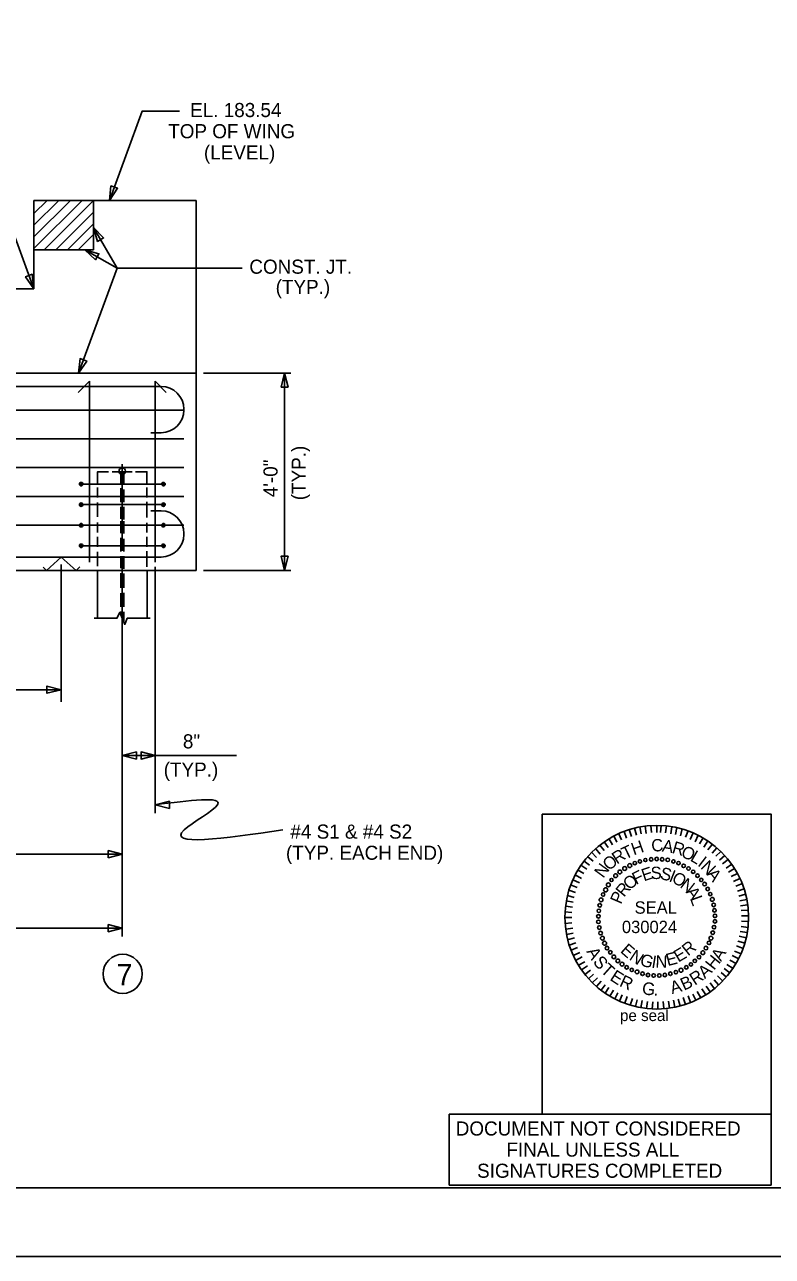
# Model space of a CAD drawing. Extents: x -41 to 251, y -169 to 237.
# Drawn here: x 134.78 to 149.93, y -50.55 to -25.59 of the extents above; entities that cross this region are included whole.
import ezdxf

# ---------------------------------------------------------------- set-up
doc = ezdxf.new("R2010")
doc.units = 0
for name, color, linetype in [('Arrowhead Terminators', 7, 'Continuous'), ('Arrowhead Terminators CELL', 7, 'Continuous'), ('Beam Bolsters CELL', 7, 'Continuous'), ('Dimension Lines', 7, 'Continuous'), ('Mis Object Lines', 7, 'Continuous'), ('Peseal', 7, 'Continuous'), ('Plan Sheet CELL', 7, 'Continuous'), ('Plot Shape CELL', 7, 'Continuous'), ('Rebar Lines', 7, 'Continuous'), ('Rebar Lines CELL', 7, 'Continuous'), ('Sheet Sticker Exception Certification CELL', 7, 'Continuous'), ('Text', 7, 'Continuous'), ('Title Text', 7, 'Continuous'), ('User Information Notes', 7, 'Continuous'), ('User Information Notes CELL', 7, 'Continuous')]:
    doc.layers.add(name, color=color, linetype=linetype)

msp = doc.modelspace()

# ---------------------------------------------------------------- linework, layer by layer
at = {"layer": 'Arrowhead Terminators'}
for points in [[(139.98, -32.938), (140.052, -32.652), (140.123, -32.938)], [(140.123, -36.366), (140.052, -36.652), (139.98, -36.366)], [(136.477, -42.474), (136.763, -42.402), (136.477, -42.331)]]:
    msp.add_lwpolyline(points, close=True, dxfattribs=at)
at = {"layer": 'Arrowhead Terminators CELL'}
for points in [[(136.501, -29.152), (136.667, -28.908), (136.532, -28.859)], [(136.18, -29.701), (136.261, -29.985), (136.385, -29.914)], [(136.006, -30.152), (136.218, -30.357), (136.29, -30.233)], [(134.971, -30.944), (134.94, -30.65), (134.805, -30.7)], [(135.876, -32.652), (136.042, -32.408), (135.908, -32.359)], [(135.522, -39.069), (135.236, -39.141), (135.236, -38.997)], [(136.763, -40.402), (137.049, -40.331), (137.049, -40.474)], [(137.43, -40.402), (137.143, -40.474), (137.143, -40.331)], [(137.43, -41.402), (137.716, -41.474), (137.716, -41.331)], [(136.763, -43.902), (136.477, -43.831), (136.477, -43.974)]]:
    msp.add_lwpolyline(points, close=True, dxfattribs=at)
at = {"layer": 'Beam Bolsters CELL'}
for p, q in [((135.522, -36.381), (135.229, -36.654)), ((135.83, -36.653), (135.522, -36.381)), ((135.229, -36.654), (135.158, -36.583)), ((135.901, -36.582), (135.83, -36.653))]:
    msp.add_line(p, q, dxfattribs=at)
at = {"layer": 'Dimension Lines'}
for p, q in [((136.18, -29.701), (136.657, -30.528)), ((136.006, -30.152), (136.657, -30.528)), ((136.657, -30.528), (139.191, -30.528)), ((140.177, -32.652), (138.406, -32.652)), ((140.052, -32.652), (140.052, -36.652)), ((135.522, -36.533), (135.522, -39.313)), ((136.763, -36.652), (136.763, -44.069)), ((137.43, -36.579), (137.43, -41.569)), ((138.406, -36.652), (140.177, -36.652)), ((135.522, -39.069), (129.716, -39.069)), ((137.43, -40.402), (136.763, -40.402)), ((139.075, -40.402), (137.43, -40.402)), ((136.763, -42.402), (130.763, -42.402)), ((124.763, -43.902), (136.763, -43.902))]:
    msp.add_line(p, q, dxfattribs=at)
for points in [[(136.501, -29.152), (137.166, -27.341), (137.923, -27.341)], [(134.971, -30.944), (134.091, -28.546), (133.591, -28.546)], [(135.876, -32.652), (136.657, -30.528)]]:
    msp.add_lwpolyline(points, dxfattribs=at)
msp.add_circle((136.77, -44.828), 0.397, dxfattribs=at)
msp.add_spline([(137.43, -41.402), (138.694, -41.402), (138.017, -41.91), (140.014, -41.91)], degree=3, dxfattribs=at)
at = {"layer": 'Mis Object Lines'}
for p, q in [((134.971, -30.128), (135.947, -29.152)), ((134.971, -29.657), (135.476, -29.152)), ((134.971, -29.421), (135.24, -29.152)), ((134.971, -29.152), (134.971, -30.944)), ((134.971, -29.893), (135.712, -29.152)), ((138.263, -29.152), (134.971, -29.152)), ((135.183, -30.152), (136.18, -29.156)), ((136.18, -29.152), (136.18, -30.152)), ((138.263, -29.152), (138.263, -32.652)), ((135.419, -30.152), (136.18, -29.391)), ((135.655, -30.152), (136.18, -29.627)), ((135.869, -30.152), (136.18, -29.842)), ((136.18, -30.152), (134.971, -30.152)), ((125.859, -30.944), (134.971, -30.944)), ((99.263, -32.652), (138.263, -32.652)), ((138.263, -36.652), (138.263, -32.652)), ((132.886, -36.652), (138.263, -36.652))]:
    msp.add_line(p, q, dxfattribs=at)
at = {"layer": 'Peseal'}
for p, q in [((147.081, -42.043), (147.036, -41.9)), ((147.179, -42.016), (147.143, -41.873)), ((147.277, -41.99), (147.251, -41.846)), ((147.376, -41.981), (147.358, -41.838)), ((147.483, -41.963), (147.474, -41.82)), ((147.591, -41.963), (147.591, -41.82)), ((147.671, -41.963), (147.68, -41.82)), ((147.769, -41.972), (147.787, -41.829)), ((147.877, -41.99), (147.895, -41.846)), ((147.975, -42.007), (148.002, -41.864)), ((148.074, -42.034), (148.109, -41.891)), ((148.172, -42.061), (148.226, -41.927)), ((146.607, -42.267), (146.526, -42.151)), ((146.696, -42.213), (146.624, -42.088)), ((146.785, -42.16), (146.723, -42.034)), ((146.875, -42.115), (146.821, -41.99)), ((146.982, -42.079), (146.929, -41.945)), ((148.27, -42.106), (148.333, -41.972)), ((148.369, -42.151), (148.431, -42.016)), ((148.458, -42.195), (148.53, -42.07)), ((148.548, -42.258), (148.628, -42.133)), ((146.374, -42.473), (146.267, -42.365)), ((146.446, -42.401), (146.356, -42.294)), ((146.526, -42.33), (146.437, -42.222)), ((148.628, -42.312), (148.718, -42.204)), ((148.718, -42.383), (148.807, -42.276)), ((148.789, -42.446), (148.888, -42.347)), ((148.861, -42.526), (148.968, -42.428)), ((146.177, -42.705), (146.052, -42.625)), ((146.231, -42.625), (146.124, -42.544)), ((146.302, -42.544), (146.195, -42.455)), ((148.923, -42.598), (149.04, -42.508)), ((148.995, -42.687), (149.111, -42.607)), ((146.025, -42.983), (145.891, -42.92)), ((146.07, -42.893), (145.936, -42.822)), ((146.115, -42.795), (145.989, -42.723)), ((149.049, -42.768), (149.165, -42.696)), ((149.102, -42.857), (149.228, -42.795)), ((149.147, -42.956), (149.272, -42.893)), ((145.945, -43.179), (145.81, -43.135)), ((145.98, -43.081), (145.846, -43.027)), ((149.192, -43.054), (149.326, -43)), ((149.228, -43.152), (149.362, -43.108)), ((145.9, -43.376), (145.757, -43.349)), ((145.918, -43.278), (145.784, -43.242)), ((149.254, -43.251), (149.389, -43.215)), ((149.272, -43.349), (149.415, -43.322)), ((149.29, -43.448), (149.433, -43.43)), ((145.873, -43.582), (145.73, -43.573)), ((145.882, -43.475), (145.748, -43.457)), ((149.299, -43.546), (149.442, -43.537)), ((149.308, -43.653), (149.451, -43.653)), ((145.873, -43.689), (145.73, -43.689)), ((145.873, -43.797), (145.73, -43.806)), ((145.891, -43.904), (145.748, -43.922)), ((149.299, -43.868), (149.442, -43.886)), ((149.308, -43.761), (149.451, -43.77)), ((145.9, -44.002), (145.766, -44.029)), ((145.927, -44.101), (145.784, -44.136)), ((149.236, -44.163), (149.38, -44.208)), ((149.263, -44.065), (149.406, -44.101)), ((149.281, -43.967), (149.424, -43.993)), ((145.954, -44.199), (145.819, -44.244)), ((145.989, -44.297), (145.855, -44.351)), ((146.034, -44.396), (145.9, -44.459)), ((149.165, -44.369), (149.299, -44.423)), ((149.21, -44.262), (149.344, -44.315)), ((146.079, -44.485), (145.945, -44.557)), ((146.132, -44.584), (146.007, -44.655)), ((146.186, -44.664), (146.07, -44.745)), ((149.013, -44.637), (149.138, -44.718)), ((149.075, -44.548), (149.201, -44.62)), ((149.12, -44.459), (149.254, -44.521)), ((146.249, -44.754), (146.132, -44.843)), ((146.311, -44.834), (146.213, -44.924)), ((146.392, -44.906), (146.285, -45.013)), ((148.825, -44.87), (148.932, -44.977)), ((148.897, -44.798), (149.004, -44.897)), ((148.959, -44.718), (149.075, -44.807)), ((146.463, -44.977), (146.374, -45.085)), ((146.544, -45.049), (146.463, -45.156)), ((146.624, -45.103), (146.544, -45.219)), ((146.714, -45.156), (146.642, -45.281)), ((148.414, -45.183), (148.485, -45.317)), ((148.503, -45.129), (148.583, -45.255)), ((148.592, -45.076), (148.673, -45.192)), ((148.673, -45.013), (148.762, -45.129)), ((148.753, -44.951), (148.843, -45.049)), ((146.803, -45.21), (146.741, -45.335)), ((146.893, -45.255), (146.839, -45.38)), ((146.991, -45.29), (146.946, -45.425)), ((147.099, -45.326), (147.054, -45.46)), ((147.197, -45.353), (147.161, -45.487)), ((147.295, -45.371), (147.269, -45.514)), ((147.403, -45.389), (147.385, -45.532)), ((147.51, -45.398), (147.501, -45.541)), ((147.617, -45.398), (147.617, -45.541)), ((147.725, -45.389), (147.734, -45.532)), ((147.832, -45.38), (147.85, -45.523)), ((147.93, -45.362), (147.957, -45.505)), ((148.029, -45.344), (148.065, -45.478)), ((148.127, -45.308), (148.172, -45.451)), ((148.226, -45.273), (148.279, -45.407)), ((148.324, -45.237), (148.387, -45.362))]:
    msp.add_line(p, q, dxfattribs=at)
for centre, radius in [((146.942, -42.692), 0.0385), ((147.045, -42.634), 0.04), ((147.148, -42.584), 0.0341), ((147.251, -42.549), 0.0326), ((147.362, -42.522), 0.0316), ((147.479, -42.508), 0.0361), ((147.591, -42.499), 0.0358), ((147.702, -42.508), 0.0361), ((147.814, -42.517), 0.0369), ((147.93, -42.549), 0.0326), ((148.033, -42.584), 0.0341), ((148.136, -42.638), 0.0361), ((148.235, -42.692), 0.0361), ((146.674, -42.924), 0.0316), ((146.759, -42.839), 0.038), ((146.844, -42.763), 0.0385), ((148.329, -42.759), 0.0349), ((148.418, -42.839), 0.0349), ((148.494, -42.924), 0.0349), ((146.504, -43.22), 0.0341), ((146.557, -43.126), 0.0412), ((146.611, -43.023), 0.0385), ((148.561, -43.009), 0.0361), ((148.624, -43.108), 0.0361), ((148.677, -43.211), 0.0341), ((146.437, -43.439), 0.0369), ((146.463, -43.327), 0.0382), ((148.718, -43.318), 0.0382), ((148.745, -43.43), 0.0369), ((146.41, -43.662), 0.0358), ((146.419, -43.551), 0.0361), ((148.762, -43.542), 0.0361), ((148.771, -43.653), 0.0358), ((146.41, -43.774), 0.0361), ((146.428, -43.89), 0.0361), ((148.753, -43.882), 0.0361), ((148.771, -43.765), 0.0361), ((146.454, -44.002), 0.0369), ((146.49, -44.105), 0.0382), ((146.535, -44.208), 0.04), ((148.651, -44.199), 0.0361), ((148.691, -44.105), 0.0382), ((148.727, -43.993), 0.0369), ((146.584, -44.306), 0.0361), ((146.651, -44.391), 0.0349), ((148.525, -44.4), 0.0385), ((148.588, -44.306), 0.0361), ((146.723, -44.485), 0.038), ((146.803, -44.566), 0.038), ((146.888, -44.633), 0.0385), ((146.982, -44.696), 0.0361), ((148.19, -44.696), 0.0361), ((148.284, -44.637), 0.0349), ((148.364, -44.566), 0.0349), ((148.449, -44.49), 0.0349), ((147.085, -44.749), 0.0341), ((147.192, -44.789), 0.0382), ((147.304, -44.825), 0.0369), ((147.416, -44.852), 0.0361), ((147.528, -44.861), 0.0358), ((147.644, -44.861), 0.0358), ((147.756, -44.852), 0.0361), ((147.868, -44.825), 0.0369), ((147.98, -44.794), 0.0341), ((148.083, -44.754), 0.04)]:
    msp.add_circle(centre, radius, dxfattribs=at)
at = {"layer": 'Plan Sheet CELL'}
msp.add_line((88.128, -49.166), (161.409, -49.166), dxfattribs=at)
at = {"layer": 'Plot Shape CELL'}
msp.add_lwpolyline([(85.715, -0.174), (161.429, -0.174), (161.429, -50.554), (85.715, -50.554)], close=True, dxfattribs=at)
at = {"layer": 'Rebar Lines'}
for p, q in [((99.97, -32.923), (137.551, -32.923)), ((136.096, -32.819), (135.872, -33.043)), ((136.096, -36.485), (136.096, -32.819)), ((137.43, -36.485), (137.43, -32.819)), ((137.43, -32.819), (137.654, -33.043)), ((117.55, -33.402), (138.009, -33.402)), ((117.55, -33.986), (138.009, -33.986)), ((117.55, -34.569), (138.009, -34.569)), ((136.732, -34.895), (136.732, -34.652)), ((136.763, -34.501), (136.763, -36.257)), ((136.795, -34.901), (136.795, -34.652)), ((117.55, -35.152), (138.009, -35.152)), ((136.732, -35.267), (136.732, -34.988)), ((136.795, -35.267), (136.795, -35.011)), ((136.732, -35.609), (136.732, -35.36)), ((136.795, -35.621), (136.795, -35.36)), ((136.732, -35.895), (136.732, -35.652)), ((136.795, -35.901), (136.795, -35.652)), ((117.55, -35.735), (138.009, -35.735)), ((136.732, -36.267), (136.732, -35.988)), ((136.795, -36.267), (136.795, -36.011)), ((99.97, -36.381), (137.551, -36.381)), ((136.732, -36.609), (136.732, -36.36)), ((136.763, -36.362), (136.763, -36.652)), ((136.795, -36.621), (136.795, -36.36)), ((136.262, -36.669), (136.262, -37.621)), ((137.264, -36.669), (137.264, -37.621)), ((136.732, -37.004), (136.732, -36.708)), ((136.763, -36.722), (136.763, -37.928)), ((136.795, -37.004), (136.795, -36.714)), ((136.732, -37.388), (136.732, -37.115)), ((136.795, -37.388), (136.795, -37.109)), ((136.732, -37.556), (136.732, -37.481)), ((136.795, -37.705), (136.795, -37.492))]:
    msp.add_line(p, q, dxfattribs=at)
for points in [[(136.262, -34.886), (136.262, -34.652), (136.485, -34.652)], [(136.561, -34.652), (136.96, -34.652)], [(137.03, -34.652), (137.262, -34.652), (137.262, -34.899)], [(136.262, -35.176), (136.262, -34.968)], [(137.262, -34.974), (137.262, -35.173)], [(136.262, -35.564), (136.262, -35.272)], [(137.262, -35.259), (137.262, -35.58)], [(136.262, -35.886), (136.262, -35.678)], [(137.262, -35.684), (137.262, -35.883)], [(136.262, -36.176), (136.262, -35.968)], [(137.262, -35.974), (137.262, -36.173)], [(136.262, -36.564), (136.262, -36.272)], [(137.262, -36.259), (137.262, -36.58)], [(136.193, -37.622), (136.655, -37.622), (136.71, -37.502), (136.812, -37.747), (136.863, -37.622), (137.33, -37.622)]]:
    msp.add_lwpolyline(points, dxfattribs=at)
msp.add_circle((136.763, -34.641), 0.066, dxfattribs=at)
at = {"layer": 'Rebar Lines CELL'}
for p, q in [((138.009, -33.402), (138.009, -33.381)), ((137.342, -33.86), (137.551, -33.86)), ((137.596, -34.902), (135.93, -34.902)), ((137.596, -35.319), (135.93, -35.319)), ((137.342, -35.444), (137.551, -35.444)), ((137.596, -35.735), (135.93, -35.735)), ((138.009, -35.902), (138.009, -35.923)), ((137.596, -36.152), (135.93, -36.152))]:
    msp.add_line(p, q, dxfattribs=at)
for points in [[(135.93, -34.867), (135.916, -34.87), (135.905, -34.877), (135.897, -34.889), (135.894, -34.902), (135.897, -34.916), (135.905, -34.927), (135.916, -34.935), (135.93, -34.937), (135.943, -34.935), (135.955, -34.927), (135.962, -34.916), (135.965, -34.902), (135.962, -34.889), (135.955, -34.877), (135.943, -34.87), (135.93, -34.867), (135.93, -34.902), (135.93, -34.937), (135.916, -34.935), (135.93, -34.902), (135.905, -34.927), (135.897, -34.916), (135.93, -34.902), (135.894, -34.902), (135.897, -34.889), (135.93, -34.902), (135.905, -34.877), (135.916, -34.87), (135.93, -34.902), (135.943, -34.87), (135.955, -34.877), (135.93, -34.902), (135.962, -34.889), (135.965, -34.902), (135.93, -34.902), (135.962, -34.916), (135.955, -34.927), (135.93, -34.902), (135.943, -34.935)], [(137.596, -34.867), (137.583, -34.87), (137.571, -34.877), (137.564, -34.889), (137.561, -34.902), (137.564, -34.916), (137.571, -34.927), (137.583, -34.935), (137.596, -34.937), (137.61, -34.935), (137.621, -34.927), (137.629, -34.916), (137.632, -34.902), (137.629, -34.889), (137.621, -34.877), (137.61, -34.87), (137.596, -34.867), (137.596, -34.902), (137.596, -34.937), (137.583, -34.935), (137.596, -34.902), (137.571, -34.927), (137.564, -34.916), (137.596, -34.902), (137.561, -34.902), (137.564, -34.889), (137.596, -34.902), (137.571, -34.877), (137.583, -34.87), (137.596, -34.902), (137.61, -34.87), (137.621, -34.877), (137.596, -34.902), (137.629, -34.889), (137.632, -34.902), (137.596, -34.902), (137.629, -34.916), (137.621, -34.927), (137.596, -34.902), (137.61, -34.935)], [(135.93, -35.284), (135.916, -35.286), (135.905, -35.294), (135.897, -35.305), (135.894, -35.319), (135.897, -35.332), (135.905, -35.344), (135.916, -35.351), (135.93, -35.354), (135.943, -35.351), (135.955, -35.344), (135.962, -35.332), (135.965, -35.319), (135.962, -35.305), (135.955, -35.294), (135.943, -35.286), (135.93, -35.284), (135.93, -35.319), (135.93, -35.354), (135.916, -35.351), (135.93, -35.319), (135.905, -35.344), (135.897, -35.332), (135.93, -35.319), (135.894, -35.319), (135.897, -35.305), (135.93, -35.319), (135.905, -35.294), (135.916, -35.286), (135.93, -35.319), (135.943, -35.286), (135.955, -35.294), (135.93, -35.319), (135.962, -35.305), (135.965, -35.319), (135.93, -35.319), (135.962, -35.332), (135.955, -35.344), (135.93, -35.319), (135.943, -35.351)], [(137.596, -35.284), (137.583, -35.286), (137.571, -35.294), (137.564, -35.305), (137.561, -35.319), (137.564, -35.332), (137.571, -35.344), (137.583, -35.351), (137.596, -35.354), (137.61, -35.351), (137.621, -35.344), (137.629, -35.332), (137.632, -35.319), (137.629, -35.305), (137.621, -35.294), (137.61, -35.286), (137.596, -35.284), (137.596, -35.319), (137.596, -35.354), (137.583, -35.351), (137.596, -35.319), (137.571, -35.344), (137.564, -35.332), (137.596, -35.319), (137.561, -35.319), (137.564, -35.305), (137.596, -35.319), (137.571, -35.294), (137.583, -35.286), (137.596, -35.319), (137.61, -35.286), (137.621, -35.294), (137.596, -35.319), (137.629, -35.305), (137.632, -35.319), (137.596, -35.319), (137.629, -35.332), (137.621, -35.344), (137.596, -35.319), (137.61, -35.351)], [(135.93, -35.7), (135.916, -35.703), (135.905, -35.711), (135.897, -35.722), (135.894, -35.735), (135.897, -35.749), (135.905, -35.76), (135.916, -35.768), (135.93, -35.771), (135.943, -35.768), (135.955, -35.76), (135.962, -35.749), (135.965, -35.735), (135.962, -35.722), (135.955, -35.711), (135.943, -35.703), (135.93, -35.7), (135.93, -35.735), (135.93, -35.771), (135.916, -35.768), (135.93, -35.735), (135.905, -35.76), (135.897, -35.749), (135.93, -35.735), (135.894, -35.735), (135.897, -35.722), (135.93, -35.735), (135.905, -35.711), (135.916, -35.703), (135.93, -35.735), (135.943, -35.703), (135.955, -35.711), (135.93, -35.735), (135.962, -35.722), (135.965, -35.735), (135.93, -35.735), (135.962, -35.749), (135.955, -35.76), (135.93, -35.735), (135.943, -35.768)], [(137.596, -35.7), (137.583, -35.703), (137.571, -35.711), (137.564, -35.722), (137.561, -35.735), (137.564, -35.749), (137.571, -35.76), (137.583, -35.768), (137.596, -35.771), (137.61, -35.768), (137.621, -35.76), (137.629, -35.749), (137.632, -35.735), (137.629, -35.722), (137.621, -35.711), (137.61, -35.703), (137.596, -35.7), (137.596, -35.735), (137.596, -35.771), (137.583, -35.768), (137.596, -35.735), (137.571, -35.76), (137.564, -35.749), (137.596, -35.735), (137.561, -35.735), (137.564, -35.722), (137.596, -35.735), (137.571, -35.711), (137.583, -35.703), (137.596, -35.735), (137.61, -35.703), (137.621, -35.711), (137.596, -35.735), (137.629, -35.722), (137.632, -35.735), (137.596, -35.735), (137.629, -35.749), (137.621, -35.76), (137.596, -35.735), (137.61, -35.768)], [(135.93, -36.117), (135.916, -36.12), (135.905, -36.127), (135.897, -36.139), (135.894, -36.152), (135.897, -36.166), (135.905, -36.177), (135.916, -36.185), (135.93, -36.187), (135.943, -36.185), (135.955, -36.177), (135.962, -36.166), (135.965, -36.152), (135.962, -36.139), (135.955, -36.127), (135.943, -36.12), (135.93, -36.117), (135.93, -36.152), (135.93, -36.187), (135.916, -36.185), (135.93, -36.152), (135.905, -36.177), (135.897, -36.166), (135.93, -36.152), (135.894, -36.152), (135.897, -36.139), (135.93, -36.152), (135.905, -36.127), (135.916, -36.12), (135.93, -36.152), (135.943, -36.12), (135.955, -36.127), (135.93, -36.152), (135.962, -36.139), (135.965, -36.152), (135.93, -36.152), (135.962, -36.166), (135.955, -36.177), (135.93, -36.152), (135.943, -36.185)], [(137.596, -36.117), (137.583, -36.12), (137.571, -36.127), (137.564, -36.139), (137.561, -36.152), (137.564, -36.166), (137.571, -36.177), (137.583, -36.185), (137.596, -36.187), (137.61, -36.185), (137.621, -36.177), (137.629, -36.166), (137.632, -36.152), (137.629, -36.139), (137.621, -36.127), (137.61, -36.12), (137.596, -36.117), (137.596, -36.152), (137.596, -36.187), (137.583, -36.185), (137.596, -36.152), (137.571, -36.177), (137.564, -36.166), (137.596, -36.152), (137.561, -36.152), (137.564, -36.139), (137.596, -36.152), (137.571, -36.127), (137.583, -36.12), (137.596, -36.152), (137.61, -36.12), (137.621, -36.127), (137.596, -36.152), (137.629, -36.139), (137.632, -36.152), (137.596, -36.152), (137.629, -36.166), (137.621, -36.177), (137.596, -36.152), (137.61, -36.185)]]:
    msp.add_lwpolyline(points, dxfattribs=at)
for centre, start, end in [((137.551, -33.381), 0, 90), ((137.551, -33.402), 270, 0), ((137.551, -35.902), 0, 90), ((137.551, -35.923), 270, 0)]:
    msp.add_arc(centre, 0.458, start, end, dxfattribs=at)
at = {"layer": 'Sheet Sticker Exception Certification CELL'}
msp.add_lwpolyline([(143.386, -47.673), (149.909, -47.673), (149.909, -49.108), (143.386, -49.108)], close=True, dxfattribs=at)
at = {"layer": 'Text'}
msp.add_line((138.263, -36.652), (138.263, -36.652), dxfattribs=at)
at = {"layer": 'User Information Notes'}
msp.add_line((147.591, -43.68), (147.591, -43.68), dxfattribs=at)
at = {"layer": 'User Information Notes CELL'}
msp.add_line((147.591, -43.68), (147.591, -43.68), dxfattribs=at)
msp.add_lwpolyline([(145.272, -41.591), (149.909, -41.591), (149.909, -47.673), (145.272, -47.673)], close=True, dxfattribs=at)
msp.add_circle((147.591, -43.68), 1.861, dxfattribs=at)

# ---------------------------------------------------------------- texts
at = {"layer": 'Peseal'}
for s, height, rotation, p in [('H', 0.25, 18.9162, (147.125, -42.428)), ('C', 0.25, 4.8625, (147.492, -42.356)), ('A', 0.25, 350.8088, (147.689, -42.347)), ('R', 0.25, 343.7819, (147.886, -42.374)), ('R', 0.25, 32.9699, (146.785, -42.616)), ('T', 0.25, 25.943, (146.955, -42.517)), ('O', 0.25, 336.7551, (148.065, -42.446)), ('L', 0.25, 329.7282, (148.253, -42.526)), ('N', 0.25, 54.0504, (146.508, -42.902)), ('O', 0.25, 39.9967, (146.624, -42.75)), ('E', 0.25, 18.4448, (147.331, -42.956)), ('S', 0.25, 2.3789, (147.474, -42.911)), ('S', 0.25, 346.313, (147.644, -42.902)), ('I', 0.25, 322.7014, (148.405, -42.625)), ('N', 0.25, 315.6745, (148.467, -42.678)), ('O', 0.25, 42.5436, (147.045, -43.144)), ('F', 0.25, 26.4777, (147.17, -43.027)), ('I', 0.25, 338.28, (147.823, -42.947)), ('O', 0.25, 330.2471, (147.877, -42.956)), ('N', 0.25, 322.2141, (148.047, -43.063)), ('A', 0.25, 308.6477, (148.592, -42.813)), ('P', 0.25, 66.6424, (146.866, -43.43)), ('R', 0.25, 50.5765, (146.929, -43.287)), ('A', 0.25, 306.1483, (148.172, -43.17)), ('L', 0.25, 290.0824, (148.261, -43.296)), ('R', 0.25, 38.6997, (148.226, -44.476)), ('A', 0.254, 300.3993, (146.16, -44.375)), ('E', 0.25, 318.5179, (146.839, -44.378)), ('N', 0.25, 326.5361, (147.018, -44.53)), ('G', 0.25, 342.5725, (147.233, -44.646)), ('E', 0.25, 14.6452, (147.814, -44.673)), ('E', 0.25, 30.6815, (148.029, -44.602)), ('A', 0.254, 59.6007, (148.895, -44.59)), ('S', 0.254, 309.4349, (146.287, -44.591)), ('T', 0.254, 318.1096, (146.439, -44.777)), ('I', 0.25, 350.5906, (147.474, -44.7)), ('N', 0.25, 358.6088, (147.564, -44.7)), ('A', 0.254, 42.3241, (148.566, -44.937)), ('H', 0.254, 51.3597, (148.751, -44.768)), ('E', 0.254, 327.1453, (146.625, -44.944)), ('R', 0.254, 335.458, (146.818, -45.07)), ('B', 0.254, 24.8312, (148.143, -45.172)), ('R', 0.254, 33.5776, (148.363, -45.07)), ('G', 0.254, 353.3858, (147.284, -45.241)), ('A', 0.254, 15.7955, (147.902, -45.24)), ('.', 0.254, 2.1323, (147.525, -45.269))]:
    msp.add_text(s, height=height, rotation=rotation, dxfattribs=at).set_placement(p)
for s, p in [('SEAL', (147.143, -43.609)), ('030024', (146.886, -44.002))]:
    msp.add_text(s, height=0.2505, dxfattribs=at).set_placement(p)
at = {"layer": 'Sheet Sticker Exception Certification CELL'}
for s, p in [('DOCUMENT NOT CONSIDERED', (143.52, -48.105)), ('FINAL UNLESS ALL', (144.547, -48.533)), ('SIGNATURES COMPLETED', (143.952, -48.961))]:
    msp.add_text(s, height=0.28561, dxfattribs=at).set_placement(p)
at = {"layer": 'Text'}
for s, p in [('EL. 183.54', (138.138, -27.464)), ('TOP OF WING', (137.693, -27.893)), ('(LEVEL)', (138.417, -28.322)), ('CONST. JT.', (139.337, -30.639)), ('(TYP.)', (139.87, -31.05)), ('8"', (137.991, -40.259)), ('(TYP.)', (137.602, -40.831)), ('#4 S1 & #4 S2', (140.169, -42.088)), ('(TYP. EACH END)', (140.079, -42.517))]:
    msp.add_text(s, height=0.286, dxfattribs=at).set_placement(p)
for s, p in [('(TYP.)', (140.481, -35.229)), ('4\'-0"', (139.909, -35.167))]:
    msp.add_text(s, height=0.286, rotation=90, dxfattribs=at).set_placement(p)
at = {"layer": 'Title Text'}
msp.add_text('7', height=0.429, dxfattribs=at).set_placement((136.648, -45.059))
at = {"layer": 'User Information Notes CELL'}
msp.add_text('pe seal', height=0.229, dxfattribs=at).set_placement((146.848, -45.785))

doc.saveas('drawing.dxf')
